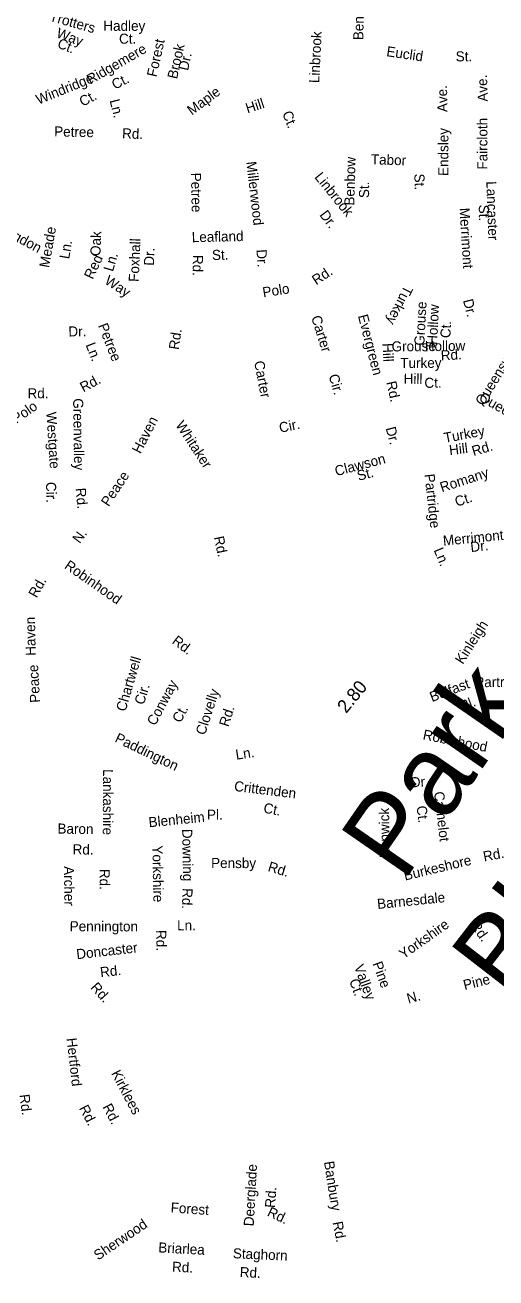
# Model space of a CAD drawing. Extents: x 1553981 to 1780076, y 812965 to 996873.
# Drawn here: x 1630892 to 1631447, y 848301 to 849777 of the extents above; entities that cross this region are included whole.
import ezdxf

# ---------------------------------------------------------------- set-up
doc = ezdxf.new("R2010")
doc.units = 0
doc.layers.add('Exist Road Non-System Type 51 Label', color=7, linetype='Continuous')
doc.layers.add('Exist Road Primary NC Service Mileage Hundredths English Label', color=7, linetype='Continuous')

msp = doc.modelspace()

# ---------------------------------------------------------------- texts
at = {"layer": 'Exist Road Non-System Type 51 Label'}
for s, height, rotation, p in [('Benbow', 11.87, 88.5686, (1631290.4, 849759.2)), ('Trotters', 11.88, 344.2558, (1630920.1, 849782.2)), ('Way', 11.88, 339.3877, (1630928, 849763.1)), ('Hadley', 11.87, 359.9596, (1630984.3, 849770.3)), ('Linbrook', 11.88, 87.1244, (1631238.5, 849708.5)), ('Ct.', 11.88, 337.6511, (1630929.1, 849751.1)), ('Ct.', 11.87, 359.9596, (1631002.8, 849755.1)), ('Forest', 11.87, 77.3902, (1631046.9, 849715.2)), ('Brook', 11.87, 77.3902, (1631071.1, 849712.9)), ('Ridgemere', 11.88, 29.9514, (1630969.1, 849706.8)), ('Dr.', 11.87, 77.3902, (1631084, 849722.7)), ('Euclid', 11.88, 351.5885, (1631317.2, 849740.5)), ('St.', 11.88, 0.6472, (1631399.4, 849734.2)), ('Windridge', 11.88, 22.0265, (1630907.9, 849683.2)), ('Ct.', 11.87, 26.9839, (1630997.9, 849700.8)), ('Ave.', 11.88, 91.9417, (1631437.2, 849687)), ('Ct.', 11.88, 27.9161, (1630959.9, 849680.7)), ('Maple', 11.88, 36.6715, (1631088.6, 849670.3)), ('Ave.', 11.87, 90.9168, (1631389.6, 849674.6)), ('Ln.', 11.87, 284.3124, (1630991.6, 849688.2)), ('Hill', 11.88, 17.919, (1631154.1, 849673)), ('Ct.', 11.88, 291.528, (1631194.8, 849673.2)), ('Faircloth', 11.88, 90.0037, (1631436.7, 849606.8)), ('Petree', 11.88, 358.7623, (1630926.3, 849645.9)), ('Rd.', 11.88, 357.6161, (1631006.2, 849643.7)), ('Endsley', 11.88, 89.915, (1631390.7, 849599.3)), ('Benbow', 11.87, 88.5686, (1631280, 849564.3)), ('Tabor', 11.87, 358.274, (1631299.3, 849613)), ('Millerwood', 11.87, 276.6315, (1631152.6, 849615.8)), ('Petree', 11.88, 271.1267, (1631087.5, 849603)), ('Linbrook', 11.88, 308.966, (1631232.4, 849597.7)), ('St.', 11.88, 89.7236, (1631297.3, 849573.2)), ('St.', 11.87, 271.7875, (1631350.6, 849601.9)), ('Lancaster', 11.88, 272.0991, (1631435.4, 849592.9)), ('St.', 11.88, 270.3555, (1631426.6, 849565.4)), ('Abingdon', 11.88, 331.74, (1630848.4, 849540)), ('Dr.', 11.88, 306.8444, (1631238.4, 849553.3)), ('Merrimont', 11.88, 273.5544, (1631403.8, 849561.4)), ('Meade', 11.88, 80.1867, (1630920.4, 849490.6)), ('Oak', 11.88, 87.8039, (1630980.8, 849504.8)), ('Leafland', 11.88, 1.3097, (1631088.6, 849521.2)), ('Ln.', 11.88, 80.1867, (1630944, 849500.8)), ('Foxhall', 11.88, 87.7242, (1631026, 849474.3)), ('Red', 11.88, 64.6867, (1630971.7, 849476.7)), ('Ln.', 11.88, 73.314, (1630995.5, 849485.9)), ('Dr.', 11.88, 87.3446, (1631043.9, 849493.3)), ('Rd.', 11.88, 268.963, (1631089.9, 849506.4)), ('St.', 11.88, 1.3097, (1631112.4, 849500.2)), ('Dr.', 11.88, 273.9853, (1631164.6, 849512.4)), ('Rd.', 11.88, 33.2841, (1631235, 849470.3)), ('Way', 11.88, 327.2036, (1630984.8, 849473.1)), ('Polo', 11.88, 8.9733, (1631172.8, 849456.2)), ('Turkey', 11.88, 243.34, (1631339, 849471.2)), ('Grouse', 11.87, 86.9084, (1631362.3, 849399.1)), ('Hollow', 11.87, 86.9084, (1631377.3, 849400.1)), ('Dr.', 11.87, 284.1093, (1631407.9, 849452.7)), ('Carter', 11.88, 287.3465, (1631229, 849432.8)), ('Evergreen', 11.88, 284.4283, (1631284.1, 849434.5)), ('Dr.', 11.88, 0.5221, (1630943.2, 849410.1)), ('Petree', 11.88, 291.4079, (1630977.9, 849423.1)), ('Rd.', 11.88, 81.1755, (1631073, 849394)), ('Ct.', 11.87, 86.9084, (1631393, 849408)), ('Ln.', 11.88, 291.4079, (1630963.2, 849400.3)), ('Hill', 11.88, 273.4504, (1631313, 849402)), ('Grouse', 11.88, 0.5219, (1631323.9, 849392.5)), ('Hollow', 11.88, 0.6391, (1631363, 849392.8)), ('Queenswood', 11.88, 58.1919, (1631431.7, 849327.7)), ('Turkey', 11.88, 0.3682, (1631334.1, 849372.9)), ('Rd.', 11.87, 3.4152, (1631382.1, 849381.8)), ('Carter', 11.88, 280.9254, (1631161.8, 849380.3)), ('Rd.', 11.87, 28.2465, (1630960.8, 849344.1)), ('Cir.', 11.87, 285.8912, (1631249.6, 849364)), ('Rd.', 11.88, 282.5237, (1631317.5, 849356.2)), ('Hill', 11.88, 359.2596, (1631338, 849354.5)), ('Ct.', 11.88, 1.1263, (1631362.6, 849349.5)), ('Rd.', 11.88, 0.2085, (1630895, 849337.2)), ('Queenswood', 11.88, 330.4298, (1631425.7, 849335.1)), ('Polo', 11.88, 34.8956, (1630881.8, 849307.1)), ('Greenvalley', 11.875, 270.7903, (1630948.7, 849337.2)), ('Westgate', 11.87, 273.7422, (1630917.1, 849320.9)), ('Haven', 11.88, 62.6985, (1631028, 849271.2)), ('Whitaker', 11.88, 303.2166, (1631068.9, 849305.9)), ('Cir.', 11.87, 11.533, (1631192.6, 849296.6)), ('Dr.', 11.87, 284.7882, (1631316.8, 849302.1)), ('Turkey', 11.87, 10.5713, (1631386.6, 849284.7)), ('Hill', 11.88, 6.8598, (1631392.3, 849270.3)), ('Rd.', 11.88, 16.6393, (1631420.4, 849269.1)), ('Clawson', 11.88, 14.763, (1631258.7, 849245.5)), ('St.', 11.88, 14.763, (1631284.9, 849240)), ('Romany', 11.88, 18.104, (1631383.1, 849226.4)), ('Cir.', 11.87, 271.5712, (1630916.7, 849238.6)), ('Peace', 11.88, 56.4048, (1630990.6, 849208.9)), ('Partridge', 11.87, 276.1828, (1631362.6, 849247.7)), ('Rd.', 11.88, 275.0307, (1630951.7, 849231.3)), ('Ct.', 11.88, 18.104, (1631400.6, 849209.4)), ('N.', 11.88, 53.2546, (1630956.4, 849165.4)), ('Merrimont', 11.88, 5.5375, (1631384.9, 849163.6)), ('Rd.', 11.87, 282.0913, (1631114.4, 849173.6)), ('Dr.', 11.88, 6.2694, (1631417.3, 849156.1)), ('Ln.', 11.88, 292.5392, (1631373.2, 849158.5)), ('Robinhood', 11.88, 325.1315, (1630937.5, 849137.7)), ('Rd.', 11.88, 60.5593, (1630905.7, 849101.3)), ('Haven', 11.88, 91.1122, (1630904.7, 849034)), ('Kinleigh', 11.88, 57.4941, (1631407.7, 849023.1)), ('Rd.', 11.88, 322.945, (1631064.3, 849049.3)), ('Chartwell', 11.88, 73.6478, (1631010.4, 848967.5)), ('Peace', 11.87, 93.243, (1630909.9, 848978.9)), ('Park', 95, 55.3199, (1631337.7, 848766.3)), ('Conway', 11.88, 61.9005, (1631045.4, 848950.7)), ('Belfast', 11.87, 20.5494, (1631371.4, 848979.3)), ('Partridge', 11.88, 0.4987, (1631422.4, 848996.9)), ('Cir.', 11.88, 72.6474, (1631031.9, 848975.4)), ('Clovelly', 11.88, 72.103, (1631104, 848939.7)), ('Ct.', 11.88, 61.9005, (1631075.2, 848954)), ('Rd.', 11.88, 72.103, (1631131.5, 848949.5)), ('Pl.', 11.87, 20.5494, (1631406.9, 848968.7)), ('Paddington', 11.87, 334.1515, (1630996.9, 848933)), ('Robinhood', 11.87, 348.6183, (1631360, 848935.6)), ('Ln.', 11.88, 8.792, (1631141, 848911.4)), ('Lankashire', 11.88, 269.7547, (1630984, 848900.4)), ('Crittenden', 11.88, 352.9259, (1631137.9, 848874.8)), ('Dr.', 11.88, 3.2994, (1631346.8, 848878.8)), ('Camelot', 11.88, 276.6291, (1631373.8, 848873.3)), ('Blvd.', 95, 52.2723, (1631464.1, 848625.1)), ('Pl.', 11.88, 0.8125, (1631106.5, 848840.7)), ('Ct.', 11.87, 349.0059, (1631172.2, 848849.3)), ('Kenwick', 11.87, 90.8295, (1631321.7, 848795.7)), ('Ct.', 11.88, 276.6291, (1631353.2, 848856.6)), ('Blenheim', 11.88, 5.658, (1631038.2, 848831.8)), ('Baron', 11.88, 358.9729, (1630930.2, 848824.5)), ('Downing', 11.88, 271.1001, (1631077.1, 848829.9)), ('Rd.', 11.88, 358.9729, (1630948, 848800)), ('Yorkshire', 11.88, 270.9876, (1631042.1, 848810.4)), ('Pensby', 11.88, 359.7648, (1631111.2, 848783.9)), ('Burkeshore', 11.88, 13.5187, (1631339.7, 848769)), ('Rd.', 11.88, 11.0387, (1631432.9, 848791.4)), ('Archer', 11.87, 270.6425, (1630937.9, 848786)), ('Rd.', 11.88, 270.0202, (1630980, 848782.9)), ('Rd.', 11.88, 343.1421, (1631177.3, 848780.4)), ('Rd.', 11.87, 267.8134, (1631077.7, 848760.3)), ('Barnesdale', 11.88, 5.8382, (1631307.4, 848735.5)), ('Pennington', 11.88, 359.8886, (1630944.7, 848709.3)), ('Ln.', 11.87, 359.8387, (1631071.2, 848710.5)), ('Yorkshire', 11.88, 35.1919, (1631337.9, 848676.1)), ('Rd.', 11.87, 305.5733, (1631416.2, 848716)), ('Rd.', 11.88, 270.8, (1631046.5, 848710.7)), ('Doncaster', 11.88, 6.5586, (1630953.2, 848676.3)), ('Rd.', 11.88, 6.5586, (1630981.2, 848655.1)), ('Valley', 11.88, 290.1029, (1631279.5, 848667.8)), ('Pine', 11.88, 290.1029, (1631301.1, 848671.2)), ('Rd.', 11.88, 312.0975, (1630968.5, 848642.6)), ('Ct.', 11.88, 290.1029, (1631273.7, 848651)), ('Pine', 11.88, 13.9339, (1631409.9, 848640)), ('N.', 11.88, 15.8077, (1631343.7, 848624)), ('Hertford', 11.88, 276.4406, (1630941, 848583.1)), ('Kirklees', 11.88, 297.7416, (1630993.2, 848542)), ('Rd.', 11.87, 277.288, (1630885.5, 848516.6)), ('Rd.', 11.88, 297.6781, (1630955.4, 848500.9)), ('Rd.', 11.88, 297.7416, (1630983, 848502.4)), ('Deerglade', 11.88, 86.8878, (1631161.4, 848361.5)), ('Banbury', 11.88, 278.8092, (1631244.2, 848437.6)), ('Rd.', 11.87, 85.6294, (1631186.4, 848383.1)), ('Forest', 11.88, 355.9707, (1631063.3, 848378.1)), ('Rd.', 11.87, 334.4122, (1631176.4, 848374.5)), ('Sherwood', 11.88, 34.0943, (1630978.1, 848321.2)), ('Rd.', 11.88, 280.8311, (1631254.3, 848366.3)), ('Briarlea', 11.87, 356.8564, (1631048.8, 848331)), ('Staghorn', 11.88, 357.4478, (1631136.7, 848324.1)), ('Rd.', 11.87, 356.8564, (1631065, 848308.3)), ('Rd.', 11.88, 357.4478, (1631144.8, 848301.9))]:
    msp.add_text(s, height=height, rotation=rotation, dxfattribs=at).set_placement(p)
at = {"layer": 'Exist Road Primary NC Service Mileage Hundredths English Label'}
msp.add_text('2.80', height=15.62, rotation=50.7845, dxfattribs=at).set_placement((1631270.4, 848965.3))

doc.saveas('drawing.dxf')
